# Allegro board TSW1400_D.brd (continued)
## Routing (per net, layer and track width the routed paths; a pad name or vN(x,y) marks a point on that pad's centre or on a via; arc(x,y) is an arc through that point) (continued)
N35303144: length 74.2
  TOP w0.254: U5.V11 v2(106.95,83.2) ; U5.AH18 v2(96.95,75.2) ; U5.U24 v2(108.95,69.2) ; U5.G18 v2(118.95,75.2)
  BOTTOM w0.254: 99.44,66.67 99.47,66.7 101.17,66.7 101.45,66.98 101.45,67.46 101.68,67.69 102.21,67.69 102.44,67.92 102.44,68.43 102.69,68.68 108.43,68.68 108.95,69.2 v2(108.95,69.2) 109.47,69.72 115.44,69.72 115.98,70.26 115.98,72.21 116.46,72.69 118.21,72.69 118.47,72.95 118.47,74.78 118.89,75.2 v2(118.95,75.2) ; 99.44,66.67 99.44,71.5 98.25,72.69 96.7,72.69 96.44,72.95 96.44,74.69 v2(96.95,75.2) 96.95,75.23 97.54,75.82 101.6,75.82 102.23,76.45 107.44,76.45 107.87,76.89 107.87,82.28 v2(106.95,83.2) ; 99.44,66.67 99.44,58.8 99.16,58.52
  BOTTOM w0.508: 99.16,58.52 96.77,56.13 C333.1 C330.1 FB4.2
N35337600: length 123.9
  TOP w0.254: U5.AC5 v2(101.95,89.2) ; U5.U5 v2(108.95,89.2) ; U5.AC30 v2(101.95,63.2) ; U5.U30 v2(108.95,63.2)
  L3-SIG1 w0.254: v2(108.95,89.2) 108.43,88.68 108.43,84.84 108.03,84.43 108.03,68.48 107.26,67.72 99.64,67.72 99.44,67.51 99.44,63.98 99.75,63.68 101.47,63.68 v2(101.95,63.2) 102.41,62.74 108.46,62.74 108.92,63.2 v2(108.95,63.2)
  L4-SIG2 w0.254: v2(108.95,89.2) 108.46,89.69 102.44,89.69 v2(101.95,89.2)
  L10-SIG4 w0.102: 101.94,89.2 v2(101.95,89.2) 101.95,90.1 101.94,90.11
  L10-SIG4 w0.254: 100.46,94.36 100.46,90.98 100.76,90.68 101.37,90.68 101.47,90.58 ; 99.52,94.36 99.44,94.28 99.44,91.01 100.74,89.71 101.14,89.71 101.66,89.2 101.94,89.2 101.94,90.11 101.47,90.58 ; 101.47,94.11 101.47,90.58
  L10-SIG4 w0.508: v1(56.39,112.01) 63.25,112.01 70.87,104.39 86.74,104.39 96.77,94.36 101.35,94.36 101.47,94.23 101.47,94.11
  vias: v1(54.1,112.01) v1(54.48,112.52) v1(54.48,111.51) v1(54.86,112.01) v1(55.24,112.52) v1(55.24,111.51) v1(55.63,112.01) v1(56.01,112.52) v1(56.01,111.51)
N38382982: length 1.7
  TOP w0.508: U2.4 196.02,139.51 C10.1
N38636606: length 1.8
  TOP w0.305: U8.1 2.55,73.16 2.13,72.75 R23.2
N38684744: length 1.9
  TOP w0.305: U8.13 4.36,76.03 3.53,76.86 C51.1
N38692023: length 8.7
  TOP w0.762: L6.1 3.95,79.62 5.11,78.46 C51.2
N38717147: length 5.5
  TOP w0.305: R29.2 6.99,77.47 5.86,76.34 U8.10
  TOP w0.508: R29.2 7.26,77.85 R30.1 R117.1
N38758692: length 2.6
  TOP w0.305: C58.1 6.73,76.33 6.36,75.95 U8.9
N38759863: length 6.3
  TOP w0.305: U8.8 7.48,74.66
  TOP w0.381: 7.48,74.66 8.13,75.31
  TOP w0.508: C57.1 11.53,75.31 8.13,75.31
  TOP w0.762: R27.1 11.58,75.31 C57.1
N38796735: length 5.6
  TOP w0.305: U8.7 7.74,73.16 v1(7.88,73.03)
  TOP w0.762: R24.1 10.82,72.26 v1(10.79,72.24) R28.1
  L3-SIG1 w0.762: v1(10.79,72.24) 9.68,72.24 8.89,73.03 v1(7.88,73.03)
N39329231: length 2.6
  TOP w0.762: TP15.1 R20.1
N39352684: length 3.1
  TOP w0.381: R21.1 27.05,116.81 R19.1 27.17,115.22 U7.16
N39357177: length 1.7
  TOP w0.381: C49.2 29.69,117.93 U7.15
N39394853: length 4.3
  TOP w0.381: U7.11 32.29,117.8 R22.2
  TOP w0.508: R22.2 32.59,117.83 32.92,118.16 32.92,118.26 33.91,119.25 R122.1
N39486748: length 2.3
  TOP w0.381: U9.3 31.64,125.49 31.11,124.97 C60.2
N39488974: length 3.9
  TOP w0.381: U9.2 31.75,126.14 31.4,126.49 R25.2
  TOP w0.508: R26.1 31.27,127.97
  TOP w0.762: 31.27,127.97 R25.2
N39500307: length 2.8
  TOP w0.381: C61.2 31.11,123.44 31.88,124.21 31.88,124.46 32.26,124.84 U9.4
N39520363: length 14
  TOP w0.432: U9.11 39.35,124.84 40.01,124.19 U9.10
  TOP w0.762: 40.01,124.19 40.14,124.05 C59.1 41.55,124.05 43.43,125.93 43.43,130.79 42.02,132.21 L7.1
N39536131: length 2
  TOP w0.381: U9.12 40.63,125.49 C59.2
N39697235: length 7.4
  TOP w0.762: C86.2 5.11,58.27 L10.1
N39697237: length 5.5
  TOP w0.305: U13.10 5.86,50.05 6.99,51.18 R43.2
  TOP w0.508: R123.1 R44.1 7.26,51.56 R43.2
N39697261: length 5.8
  TOP w0.305: v1(7.88,46.74) 7.74,46.87 U13.7
  TOP w0.762: R42.1 v1(10.95,45.95) 11.63,45.95 R40.1
  L3-SIG1 w0.762: v1(7.88,46.74) 9.02,46.74 9.8,45.95 v1(10.95,45.95)
N39697276: length 2.6
  TOP w0.305: C91.1 6.73,50.04 6.36,49.67 U13.9
N39697334: length 6.5
  TOP w0.305: U13.8 7.48,48.38
  TOP w0.381: 7.48,48.38 8.13,49.02
  TOP w0.508: 8.13,49.02 11.53,49.02 C90.1
  TOP w0.762: C90.1 13.23,49.02 R41.1
N39697425: length 1.9
  TOP w0.305: C86.1 3.53,50.57 4.36,49.74 U13.13
N39697499: length 1.8
  TOP w0.305: R39.2 2.13,46.46 2.55,46.87 U13.1
N39748772: length 14
  TOP w0.432: U15.11 57.9,124.84 58.55,124.19 U15.10
  TOP w0.762: L11.1 60.56,132.21 61.98,130.79 61.98,125.93 60.1,124.05 C97.1 58.68,124.05 58.55,124.19
N39748780: length 4.1
  TOP w0.381: R47.2 49.94,126.49 50.29,126.14 U15.2
  TOP w0.508: R48.1 49.81,127.97
  TOP w0.762: 49.81,127.97 R47.2
N39748835: length 2
  TOP w0.381: C97.2 59.17,125.49 U15.12
N39748872: length 2.3
  TOP w0.381: U15.3 50.18,125.49 49.66,124.97 C98.2
N39748888: length 2.8
  TOP w0.381: U15.4 50.8,124.84 50.42,124.46 50.42,124.21 49.66,123.44 C99.2
N40105653: length 5.6
  TOP w0.305: U10.7 7.74,111.01 v1(7.88,110.87)
  TOP w0.762: R35.1 v1(10.79,110.08) 11.51,110.08 R32.1
  L3-SIG1 w0.762: v1(7.88,110.87) 8.89,110.87 9.68,110.08 v1(10.79,110.08)
N40105663: length 8.7
  TOP w0.762: L8.1 3.95,117.59 5.11,116.43 C64.2
N40105684: length 5.5
  TOP w0.305: R33.2 6.99,115.32 5.86,114.19 U10.10
  TOP w0.508: R33.2 7.26,115.7 R36.1 R119.1
N40105708: length 2.6
  TOP w0.305: U10.9 6.36,113.8 6.73,114.17 C70.1
N40105747: length 6.3
  TOP w0.305: U10.8 7.48,112.51
  TOP w0.381: 7.48,112.51 8.13,113.16
  TOP w0.508: 8.13,113.16 11.53,113.16 C69.1
  TOP w0.762: C69.1 11.58,113.16 R34.1
N40105844: length 1.9
  TOP w0.305: U10.13 4.36,113.88 3.53,114.71 C64.1
N40105894: length 1.8
  TOP w0.305: R31.2 2.13,110.59 2.55,111.01 U10.1
N40477874: length 2.3
  TOP w0.381: U12.3 68.72,125.49 68.2,124.97 C83.2
N40477880: length 14
  TOP w0.432: U12.10 77.09,124.19 76.44,124.84 U12.11
  TOP w0.762: L9.1 79.1,132.21 80.52,130.79 80.52,125.93 78.64,124.05 C82.1 77.23,124.05 77.09,124.19
N40477882: length 3.9
  TOP w0.381: R37.2 68.48,126.49 68.83,126.14 U12.2
  TOP w0.508: R38.1 68.35,127.97
  TOP w0.762: 68.35,127.97 R37.2
N40477947: length 2
  TOP w0.381: C82.2 77.71,125.49 U12.12
N40477997: length 2.8
  TOP w0.381: C84.2 68.2,123.44 68.96,124.21 68.96,124.46 69.34,124.84 U12.4
N40549332: length 10.3
  TOP w0.178: v1(33.91,89.15) 34.04,89.02 U11.7 ; v1(34.29,84.05) 34.29,84.2 34.44,84.05 R120.2 R118.1 ; U11.9 34.04,88.02 v1(33.91,87.88)
  L3-SIG1 w0.178: v1(33.91,89.15) v1(33.91,87.88) 33.91,87.5 34.29,87.12 v1(34.29,84.05)
N40558976: length 1.5
  TOP w0.762: C74.1 14.66,113.18 R34.2
N41623470: length 17
  TOP w0.381: U16.2 92.96,136.9
  TOP w0.508: 92.96,136.9 92.96,135.76 91.44,134.24 87.22,134.24 ; 87.22,134.24 87.22,136.04 86.51,136.75 SJP1.1 ; 87.22,134.24 86.21,133.22 85.72,133.22 JP3.2
N41648199: length 29.3
  TOP w0.381: U17.2 185.04,87.38 184.94,87.27
  TOP w0.508: 176.59,87.19 177.67,88.27 178.18,88.77 178.18,93.22 179.71,94.74 SJP2.1 ; 176.59,87.19 177.93,85.85 183.51,85.85 184.94,87.27 ; 176.59,87.19 JP4.2
N44148054: length 1.8
  TOP w0.178: U5.B3 v2(123.95,91.2)
  BOTTOM w0.178: R90.2 124.7,91.95 v2(123.95,91.2)
N44148055: length 1.6
  TOP w0.178: U5.A3 v2(124.95,91.2)
  BOTTOM w0.178: R89.2 124.96,91.19 v2(124.95,91.2)
N44200403: length 46.6
  TOP w0.178: U5.T2 v2(109.95,92.2) ; U5.P1 v2(111.95,93.2) ; U5.AH1 v2(96.95,93.2) ; U5.F1 v2(119.95,93.2) ; U5.V2 v2(106.95,92.2) ; U5.P2 v2(111.95,92.2) ; U5.Y1 v2(104.95,93.2) ; U5.H2 v2(117.95,92.2) ; U5.V1 v2(106.95,93.2) ; U5.Y2 v2(104.95,92.2) ; U5.T1 v2(109.95,93.2) ; U5.H1 v2(117.95,93.2) ; U5.F2 v2(119.95,92.2) ; U5.AF1 v2(98.95,93.2) ; U5.AF2 v2(98.95,92.2) ; U5.AH2 v2(96.95,92.2)
  BOTTOM w0.178: v2(106.95,92.2) 106.93,92.2 106.43,91.69 105.46,91.69 v2(104.95,92.2) ; v2(106.95,92.2) 107.46,91.69 109.35,91.69 109.85,92.2 v2(109.95,92.2) ; v2(106.95,92.2) v2(106.95,93.2) ; v2(117.95,92.2) 118.46,91.69 119.38,91.69 119.89,92.2 v2(119.95,92.2) v2(119.95,93.2) ; v2(117.95,92.2) v2(117.95,93.2) ; v2(117.95,92.2) 117.85,92.2 117.35,91.69 112.46,91.69 v2(111.95,92.2) ; v2(104.95,92.2) v2(104.95,93.2) ; v2(104.95,92.2) 104.9,92.2 103.4,90.7 100.45,90.7 v2(98.95,92.2) ; v2(111.95,92.2) v2(111.95,93.2) ; v2(111.95,92.2) 111.88,92.2 111.38,91.69 110.46,91.69 v2(109.95,92.2) ; v2(109.95,92.2) v2(109.95,93.2) ; R91.1 96.9,93.25 v2(96.95,93.2) v2(96.95,92.2) 97.46,91.69 98.42,91.69 98.93,92.2 v2(98.95,92.2) ; v2(98.95,92.2) v2(98.95,93.2)
N44225882: length 26.5
  TOP w0.178: U5.M1 v2(113.95,93.2) ; U5.M2 v2(113.95,92.2) ; U5.AB2 v2(102.95,92.2) ; U5.AB1 v2(102.95,93.2) ; U5.K1 v2(115.95,93.2) ; U5.K2 v2(115.95,92.2) ; U5.AD2 v2(100.95,92.2) ; U5.AD1 v2(100.95,93.2)
  BOTTOM w0.178: v2(113.95,92.2) v2(113.95,93.2) ; v2(113.95,93.2) 113.94,93.2 113.41,93.73 103.48,93.73 v2(102.95,93.2) v2(102.95,92.2) 102.95,92.16 102.49,91.69 101.46,91.69 v2(100.95,92.2) v2(100.95,93.2) 100.97,93.22 R92.1 ; v2(113.95,93.2) 114.48,93.73 115.44,93.73 115.95,93.22 v2(115.95,93.2) v2(115.95,92.2)
N44253255: length 1.2
  TOP w0.178: U5.D34 v2(121.95,59.2)
  BOTTOM w0.178: R93.1 121.92,59.17 v2(121.95,59.2)
N44254573: length 1.3
  TOP w0.178: U5.AK34 v2(94.95,59.2)
  BOTTOM w0.178: v2(94.95,59.2) 94.95,58.72 R94.1
N44426490: length 4.7
  TOP w0.178: U18.5 59.13,119.1 R125.2 R124.1
N44456154: length 4.9
  TOP w0.254: U18.3 59.79,117.12 59.94,116.97 59.94,114.68 59.31,114.05 R96.2
N44466162: length 3.2
  TOP w0.254: 54.51,117.12 R97.1 ; 54.51,117.12 R98.2 ; 54.51,117.12 54.51,117.12 U18.8
N44506277: length 2.9
  TOP w0.254: C337.1 55.24,118.64 55.24,117.86 55.48,117.62 U18.7
N44658612: length 1.3
  TOP w0.178: U5.E9 v2(120.95,85.2)
  BOTTOM w0.178: R95.1 120.97,85.22 v2(120.95,85.2)
N45362819: length 24.8
  TOP w0.457: U15.7 50.53,122.89 R114.1 ; U12.7 69.07,122.89 R115.1
  TOP w0.508: v1(68.07,121.28) 68.07,121.89 R115.1 ; R114.1 v1(49.56,121.28)
  BOTTOM w0.508: v1(68.07,121.28) v1(49.56,121.28)
N45364246: length 4.9
  TOP w0.457: U9.7 31.98,122.89 R113.1
  TOP w0.508: R113.1 31.78,121.16 R121.1
N45543111: length 1.9
  BOTTOM w0.178: J13.9 R129.2
N45543118: length 1.9
  BOTTOM w0.178: 141.6,38.1 R130.2
N45543130: length 1.8
  BOTTOM w0.178: 141.6,40.64 R131.2
N45543159: length 1.8
  BOTTOM w0.178: 139.06,40.64 R132.2
N45543649: length 1.4
  TOP w0.178: DN2.2 97.98,106.87 C352.1
N45582695: length 6.5
  TOP w0.178: SJP1.2 85.09,140.46 85.47,140.84 87.25,140.84 87.76,140.33 U16.10
N45584475: length 2.2
  TOP w0.178: U17.10 SJP2.2
N45611700: length 2.3
  TOP w0.178: R72.2 D7.1
N45611745: length 10.8
  TOP w0.178: SW3.3 SW3.4 153.96,101 R85.2 153.92,99.59 C339.1 153.9,98.2 153.92,98.17
N45611776: length 10.8
  TOP w0.178: SW5.3 SW5.4 172.89,101.13 172.85,100.97 172.85,99.59 C341.1 172.82,98.2 172.85,98.17
N45611858: length 10.8
  TOP w0.178: 135.13,98.17 135.1,98.2 C342.1 135.13,99.59 R88.2 135.17,101.13 SW6.4 SW6.3
N45611860: length 2.3
  TOP w0.178: R69.2 D3.1
N45611894: length 10.8
  TOP w0.178: SW4.3 SW4.4 163.23,101 R86.2 163.19,99.59 C340.1 163.17,98.2 163.19,98.17
N45612012: length 20.1
  TOP w0.178: R79.2 28.7,18.41 29.21,17.91 U1.3 U1.6 ; R79.2 28.71,18.91 U1.1 ; R79.2 28.07,18.92 25.78,16.64 25.78,12.83 27.43,11.18 29.65,11.18 SW7.2
N45612026: length 33.5
  L4-SIG2 w0.508: SW7.8 30.91,12.49 32.51,14.1 35.31,14.1 36.91,12.49 SW7.11 42.42,17.92 42.42,28.96 J18.1
N45612034: length 17.8
  TOP w0.178: U14.1 35.57,18.91 R77.2 35.69,18.41 36.19,17.91 U14.3 U14.6 39.91,17.91 40.39,17.91 41.02,17.27 41.02,12.45 39.75,11.18 37.85,11.18 36.91,10.24 SW7.5
N45612058: length 10.8
  TOP w0.178: SW2.3 SW2.4 144.56,101.13 R84.2 144.53,99.59 C338.1 144.5,98.2 144.53,98.17
N45612265: length 2.3
  TOP w0.178: R70.2 D4.1
N45612267: length 2.3
  TOP w0.178: R71.2 D5.1
N45612353: length 2.3
  TOP w0.178: R74.2 D8.1
N45612355: length 2.3
  TOP w0.178: R75.2 D9.1
N45612432: length 2.3
  TOP w0.178: R68.2 D2.1
N45612555: length 2.3
  TOP w0.178: R73.2 D6.1
N45612557: length 2.6
  TOP w0.178: D1.1 R67.1
N45629411: length 4.8
  TOP w0.178: U5.B2 v2(123.95,92.2)
  BOTTOM w0.178: R138.1 R137.2 122.43,92.96 122.68,92.71 123.44,92.71 v2(123.95,92.2)
N45629497: length 5.9
  TOP w0.178: U5.C3 v2(122.95,91.2)
  BOTTOM w0.178: v2(122.95,91.2) 122.94,91.19 122.94,90.42 123.7,89.66 R139.1 R140.2
N45629519: length 3.8
  TOP w0.178: U5.B1 v2(123.95,93.2)
  BOTTOM w0.178: v2(123.95,93.2) 124.32,93.57 124.94,93.57 R141.2 R142.1
N45638501: length 1.9
  TOP w0.178: U19.8 R134.2
N45639686: length 26.1
  TOP w0.406: 195.66,103.68 196.22,103.12 197.99,103.12 198.54,103.68 ; 195.66,103.68 195.16,104.18 J4.1 ; 195.66,103.68 J4.3 ; 198.54,103.68 199.04,104.18 J4.2 ; 198.54,103.68 J4.4
  TOP w0.508: F2.2 R65.2 ; J4.1 194.08,104.01
  TOP w1.016: 194.08,104.01 192.28,104.01
  TOP w1.524: 192.28,104.01 186.81,109.48 F2.2
N45639690: length 2.1
  TOP w0.508: D10.1 182.37,114.87 R65.1
N45747552: length 4
  TOP w0.178: U20.10 25,140.32 25.4,140.72 25.4,141.99 26.14,142.72 R148.1
N45747567: length 1.9
  TOP w0.178: U20.5 16.85,140.32 C295.1
N45747801: length 4.5
  TOP w0.178: U20.4 R158.1 15.01,140.97 R157.2
N45748253: length 3.8
  TOP w0.508: R146.1 26.11,139.67 U20.9
  TOP w0.762: R146.1 R145.2
N45782435: length 1.3
  TOP w0.178: U5.AN2 v2(91.95,92.2)
  BOTTOM w0.178: v2(91.95,92.2) 91.95,92.2 R143.2
N45835930: length 2.7
  TOP w0.762: U6.5 77.41,109.5 77.05,109.86 Y2.3
N45836337: length 51
  TOP w0.178: JP8.2 131.83,116.71 131.83,97.66 132.21,97.28 132.21,85.46 v2(124.95,78.2) U5.A16 ; U5.F17 v2(119.95,77.2)
  BOTTOM w0.178: v2(119.95,77.2) 120,77.2 120.52,77.72 120.52,78.49 120.78,78.74 124.41,78.74 v2(124.95,78.2)
N45837320: length 4.1
  TOP w0.508: R155.1 47.5,26.29 ; 47.5,26.29 R116.2 ; 47.5,26.29 J18.3
N45842022: length 10.1
  TOP w0.178: R154.1 34.91,15.33 SW7.10
  L9-SIG3 w0.178: SW7.10 33.48,13.84 30.35,13.84 28.92,12.41 SW7.7
N45842530: length 11.6
  TOP w0.508: v1(90.55,52.2) v1(90.93,51.82) SJP3.2
  BOTTOM w0.508: v1(90.93,51.82) v1(90.55,52.2) 89.92,52.83 89.92,56.64 90.42,57.15 R144.2
N45845005: length 1.2
  TOP w0.254: U5.AN33 92.45,60.71 91.96,61.2 v2(91.95,61.2)
  BOTTOM w0.508: v2(91.95,61.2) 91.94,61.21 R144.1
N45846780: length 2.6
  TOP w0.178: R147.1 25.29,139.02 U20.8
N387611130: length 1.5
  TOP w0.762: C63.1 14.66,75.34 R27.2
N396973600: length 1.6
  TOP w0.762: C93.1 16.31,49.05 R41.2

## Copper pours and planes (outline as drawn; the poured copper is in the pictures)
0.9V on TOP (solid shape): 24.64,71.63 12.7,71.63 12.7,72.77 19.56,72.77 19.56,78.36 17.65,80.26 15.49,80.26 11.94,83.82 11.94,87.38 24.64,87.38
0.9V on L7-PWR2: 103.5,73.66 96.39,73.66 96.39,78.49 96.65,78.74 97.41,78.74 97.41,79.76 97.16,80.01 97.16,82.55 99.06,82.55 99.06,93.34 89.03,93.34 89.03,90.81 89.53,90.81 89.53,89.53 83.19,89.53 83.19,103.5 91.44,103.5 91.44,99.69 107.31,99.69 107.31,91.44 104.65,91.44 104.65,87 112.39,87 112.39,95.12 110.87,95.12 110.87,100.33 140.97,100.33 140.97,79.38 129.54,79.38 129.54,90.68 126.36,90.68 126.36,95.25 117.09,95.25 117.09,79.38 111.76,79.38 111.76,59.69 121.92,59.69 121.92,48.9 20.95,48.9 20.95,87.63 26.67,87.63 26.67,58.42 82.93,58.42 85.6,61.09 87.25,61.09 88.01,61.85 89.66,61.85 89.66,53.09 100.33,53.09 100.33,66.67 100.46,66.8 100.46,67.44 100.33,67.56 100.33,69.22 103.5,69.22
0.9V_DDR on TOP: 48.77,65.91 48.77,87.5 43.05,87.5 42.16,88.39 42.16,88.65 43.05,89.53 51.31,89.53 51.31,65.91
0.9V_DDR on BOTTOM: 51.31,65.91 48.77,65.91 48.77,86.74 43.18,86.74 43.18,89.66 39.12,89.66 39.12,90.42 51.31,90.42
1.1V on TOP (solid shape): 28.83,111.76 29.84,111.76 29.84,110.74 22.35,110.74 22.35,114.05 28.83,114.05
1.1V on L6-PWR1: 102.23,64.39 106.68,68.83 109.86,68.83 110.36,69.34 110.36,72.01 110.24,72.14 110.24,81.03 110.36,81.15 110.36,83.19 109.98,83.57 107.19,83.57 106.3,84.45 103.12,84.45 103.12,90.04 113.67,90.04 113.67,86.61 111.76,86.61 111.76,64.77 113.67,64.77 113.67,59.69 107.95,59.69 107.95,42.55 31.75,42.55 31.75,48.9 10.79,48.9 10.79,67.94 35.56,67.94 35.56,92.08 26.04,92.08 26.04,109.98 20.32,109.98 20.32,115.95 30.48,115.95 30.48,112.39 31.11,112.39 31.11,97.79 43.18,97.79 43.18,60.33 16.51,60.33 16.51,53.98 59.69,53.98 59.69,50.8 90.81,50.8 90.81,47.62 102.23,47.62
1.5V on TOP (solid shape): 36.83,128.02 33.53,128.02 33.53,126.62 32.51,126.62 32.51,129.41 27.43,129.41 27.43,133.1 36.83,133.1
1.5V on L7-PWR2: 105.28,87.63 105.28,90.81 107.95,90.81 107.95,100.33 92.08,100.33 92.08,104.14 82.55,104.14 82.55,88.9 83.19,88.9 83.19,75.56 77.47,75.56 77.47,106.05 93.98,106.05 93.98,102.62 103.5,102.62 103.5,117.6 92.71,117.6 92.71,114.3 35.18,114.3 31.11,118.36 31.11,124.21 24.51,130.81 24.51,132.72 25.15,133.35 40.01,133.35 40.01,123.83 44.45,119.38 110.24,119.38 110.24,94.49 111.76,94.49 111.76,87.63
1.8V on TOP (solid shape): 42.04,87.25 42.29,86.74 42.29,86.23 41.91,85.72 40.89,85.72 40.51,86.23 40.51,86.74 40.77,87.25 40.77,88.11 42.04,88.11
1.8V on TOP (solid shape): 25.53,120.14 21.21,116.46 21.21,109.47 12.7,109.47 12.7,110.62 19.56,110.62 19.56,116.33 14.99,121.16 12.06,121.16 12.06,125.09 25.53,125.09
1.8V on L7-PWR2: 38.1,92.71 38.1,65.28 87.12,65.28 88.01,64.39 89.03,64.39 90.3,65.66 93.6,65.66 93.6,68.33 96.39,68.33 96.39,65.41 99.69,65.41 99.69,67.82 99.57,67.94 99.57,68.58 99.69,68.71 99.69,69.85 102.87,69.85 102.87,73.03 95.76,73.03 95.76,77.47 95.5,77.72 95.5,78.61 96.01,79.12 96.52,79.12 96.52,83.82 93.73,83.82 93.73,85.72 87.63,85.72 87.63,69.85 71.12,69.85 71.12,106.68 25.4,106.68 25.4,118.87 26.67,118.87 26.67,120.65 25.4,120.65 20.07,125.98 20.07,134.11 22.48,136.53 78.11,136.53 81.92,132.72 129.16,132.72 129.16,117.98 160.02,117.98 160.02,88.27 174.62,88.27 174.62,147.96 86.36,147.96 82.55,151.76 0.64,151.76 0.64,89.53 12.7,89.53 15.88,92.71 ; 3 cut-outs
2.5V on TOP (solid shape): 35.31,112.65 36.2,112.01 36.2,111.12 35.43,110.74 34.54,110.74 33.78,111.12 33.78,112.01 34.54,112.65 34.54,113.41 35.31,113.41
2.5V on TOP (solid shape): 23.88,45.21 12.83,45.21 12.83,46.35 19.68,46.35 19.68,52.45 18.16,53.98 14.29,53.98 11.81,56.52 9.65,56.52 9.65,59.18 23.88,59.18
2.5V on L6-PWR1: 43.81,59.69 43.81,98.42 31.75,98.42 31.75,113.03 31.11,113.03 31.11,120.55 33.15,120.55 33.15,115.57 54.61,115.57 54.61,102.87 133.99,102.87 133.99,53.98 108.58,53.98 108.58,59.05 114.3,59.05 114.3,65.41 112.39,65.41 112.39,85.98 114.3,85.98 114.3,90.68 102.49,90.68 102.49,83.82 106.17,83.82 106.93,83.06 109.73,83.06 110.11,82.68 110.11,81.66 109.6,81.15 109.6,72.14 110.11,71.63 110.11,69.85 109.73,69.47 106.43,69.47 101.6,64.64 101.6,48.26 91.44,48.26 91.44,51.44 60.33,51.44 60.33,54.61 17.14,54.61 17.14,59.69
3.0V on TOP (solid shape): 55.37,128.02 52.07,128.02 52.07,126.62 51.05,126.62 51.05,129.41 45.97,129.41 45.97,133.1 55.37,133.1
3.0V on L7-PWR2: outline of 91 points within 13.34,34.29 186.06,135.89
3.3V on TOP (solid shape): 73.91,128.02 70.61,128.02 70.61,126.62 69.6,126.62 69.6,129.41 64.52,129.41 64.52,133.1 73.91,133.1
3.3V on L6-PWR1: 154.94,93.98 134.62,93.98 134.62,103.5 55.24,103.5 55.24,121.28 63.37,121.28 63.37,118.11 59.69,118.11 59.69,113.67 66.67,113.67 66.67,118.75 80.64,118.75 80.64,130.81 73.41,130.81 73.41,129.29 63.63,129.29 63.63,130.81 29.34,130.81 29.34,151.76 90.17,151.76 90.17,128.91 97.16,128.91 97.16,140.34 167,140.34 167,114.3 175.9,114.3 175.9,59.82 187.83,59.82 187.83,33.15 198.25,33.15 198.25,20.19 187.83,20.19 187.83,10.92 154.94,10.92 ; 1 cut-out
3.3V_USB on L6-PWR1: 167.64,140.97 96.52,140.97 96.52,129.54 90.81,129.54 90.81,149.86 193.68,149.86 193.68,143.51 201.29,143.51 201.29,86.36 176.53,86.36 176.53,114.94 167.64,114.94
5V_IN on TOP (solid shape): 13.84,141.73 10.92,141.73 10.92,142.75 13.84,142.75
5V_IN on TOP (solid shape): 8.89,109.6 6.35,109.6 6.22,109.73 6.22,110.36 8.89,110.36
5V_IN on TOP (solid shape): 8.89,71.75 6.35,71.75 6.22,71.88 6.22,72.52 8.89,72.52
5V_IN on TOP (solid shape): 8.89,45.47 6.35,45.47 6.22,45.59 6.22,46.23 8.89,46.23
5V_IN on TOP (solid shape): 8.89,129.41 5.33,129.41 5.33,133.35 8.89,133.35
5V_IN on TOP (solid shape): 41.4,129.41 41.4,127.64 41.02,127.25 41.02,126.75 40.13,126.75 40.13,129.41 40.26,129.54 41.27,129.54
5V_IN on TOP (solid shape): 59.94,129.41 59.94,127.64 59.56,127.25 59.56,126.75 58.67,126.75 58.67,129.41 58.8,129.54 59.82,129.54
5V_IN on TOP (solid shape): 78.49,129.41 78.49,127.64 78.11,127.25 78.11,126.75 77.22,126.75 77.22,129.41 77.34,129.54 78.36,129.54
5V_IN on TOP (solid shape): 36.07,117.98 36.07,117.09 35.26,116.46 35.26,115.7 34.54,115.7 34.54,116.46 33.66,117.09 33.66,117.98 34.42,118.36 35.31,118.36
5V_IN on TOP (solid shape): 5.97,108.2 6.22,108.2 6.86,107.7 6.86,106.81 6.48,106.43 4.83,106.43 4.45,106.81 4.45,107.7 5.08,108.2 5.31,108.2 5.31,110.24 5.97,110.24
5V_IN on TOP (solid shape): 5.97,70.36 6.22,70.36 6.86,69.85 6.86,68.96 6.48,68.58 4.83,68.58 4.45,68.96 4.45,69.85 5.08,70.36 5.3,70.36 5.3,72.39 5.97,72.39
5V_IN on TOP (solid shape): 5.97,44.07 6.22,44.07 6.86,43.56 6.86,42.67 6.48,42.29 4.83,42.29 4.45,42.67 4.45,43.56 5.08,44.07 5.32,44.07 5.32,46.1 5.97,46.1
5V_IN on TOP (solid shape): 25.4,33.02 18.03,33.02 17.65,32.64 17.65,26.92 17.02,26.29 17.02,19.94 12.7,19.94 12.7,40.01 25.4,40.01
5V_IN on TOP (solid shape): 35.69,87.12 35.31,86.74 34.8,86.74 33.91,85.85 33.91,85.6 33.53,85.09 32.51,85.09 32.13,85.6 32.13,86.11 32.38,86.49 32.38,87.38 33.53,87.38 33.66,87.25 34.04,87.25 34.42,87.63 35.69,87.63
5V_IN on L6-PWR1: 33.66,121.16 30.48,121.16 30.48,116.59 19.68,116.59 19.68,109.35 25.4,109.35 25.4,91.44 34.92,91.44 34.92,68.58 10.16,68.58 10.16,48.26 31.11,48.26 31.11,41.91 52.07,41.91 52.07,15.88 0.64,15.88 0.64,151.76 28.7,151.76 28.7,130.18 63.12,130.18 63.12,128.78 73.91,128.78 73.91,130.18 80.01,130.18 80.01,119.38 66.04,119.38 66.04,114.3 60.33,114.3 60.33,117.47 64.01,117.47 64.01,121.92 54.61,121.92 54.61,116.2 33.66,116.2 ; 1 cut-out
6.0V_OUT on TOP (solid shape): 185.29,100.97 179.2,100.97 179.2,105.28 185.29,105.28
6.0V_OUT on TOP (solid shape): 32.13,146.81 32.13,142.37 33.15,141.35 33.15,138.68 30.35,138.68 30.35,140.46 29.97,140.84 29.21,140.84 29.21,145.16 19.81,145.16 19.81,149.99 28.57,149.99
6.0V_OUT on BOTTOM: 179.32,105.28 178.05,104.01 178.05,102.23 179.32,100.97 181.36,100.97 181.36,105.28
6.0V_OUT on BOTTOM: 30.35,141.48 30.35,138.68 30.86,138.18 32.64,138.18 33.15,138.68 33.15,141.48
GND on TOP (solid shape): 7.51,111.91 6.78,111.91 6.78,111.61 7.51,111.61 7.51,111.49 3.21,111.49 3.21,111.61 3.93,111.61 3.93,111.91 3.21,111.91 3.21,111.99 7.51,111.99
GND on TOP (solid shape): 7.51,74.06 6.78,74.06 6.78,73.76 7.51,73.76 7.51,73.65 3.21,73.65 3.21,73.76 3.93,73.76 3.93,74.06 3.21,74.06 3.21,74.15 7.51,74.15
GND on TOP (solid shape): 7.51,47.78 6.78,47.78 6.78,47.47 7.51,47.47 7.51,47.36 3.21,47.36 3.21,47.47 3.93,47.47 3.93,47.78 3.21,47.78 3.21,47.85 7.51,47.85
GND on TOP: 0.38,96.8 15.24,99.19 0.38,101.57 0.38,152.02 56.5,152.02 57.91,136.9 59.32,152.02 205.36,152.02 205.36,0.38 0.38,0.38 ; 65 cut-outs
GND on BOTTOM: 0.38,0.38 0.38,96.8 15.24,99.19 0.38,101.57 0.38,152.02 56.48,152.02 57.91,136.9 59.35,152.02 205.36,152.02 205.36,0.38 ; 55 cut-outs
GND on L2-GND1: 0.38,152.02 0.38,0.38 205.36,0.38 205.36,152.02 ; 2 cut-outs
GND on L5-GND2, L11-GND4: 0.38,152.02 0.38,0.38 205.36,0.38 205.36,152.02 ; 1 cut-out
GND on L6-PWR1: 90.42,152.02 90.42,150.11 193.93,150.11 193.93,143.76 201.55,143.76 201.55,86.11 176.28,86.11 176.28,60.2 188.21,60.2 188.21,33.53 198.5,33.53 198.5,19.81 188.21,19.81 188.21,10.54 154.69,10.54 154.69,93.73 134.24,93.73 134.24,53.72 108.2,53.72 108.2,42.29 52.32,42.29 52.32,15.62 0.38,15.62 0.38,0.38 205.36,0.38 205.36,152.02
GND on L7-PWR2: 82.8,152.02 82.8,151.89 86.49,148.21 174.88,148.21 174.88,96.14 186.31,96.14 186.31,34.04 13.08,34.04 13.08,89.28 0.38,89.28 0.38,0.38 205.36,0.38 205.36,152.02
GND on L8-GND3: 0.38,152.02 0.38,0.38 205.36,0.38 205.36,152.02 ; 1 cut-out
N35337600 on TOP: 57.28,114.43 56.39,115.32 56.39,116.71 55.75,116.71 55.24,116.2 55.24,115.32 53.85,115.32 53.85,111.76 54.36,111.25 56.13,111.25 57.28,112.39
N35337600 on L10-SIG4: 56.64,111.76 56.64,112.27 56.13,112.78 54.36,112.78 53.85,112.27 53.85,111.76 54.36,111.25 56.13,111.25
N38692023 on TOP (solid shape): 5.43,75.44 4.79,75.44 4.8,77.6 5.43,77.6
N39697235 on TOP (solid shape): 5.44,49.15 4.77,49.15 4.78,51.31 5.44,51.31
N40105663 on TOP (solid shape): 5.43,113.28 4.78,113.29 4.78,115.44 5.43,115.44
N40516729 on TOP (solid shape): 10.54,17.27 18.29,17.27 18.8,16.76 18.8,12.95 17.27,11.43 12.8,11.43 10.39,13.84 6.35,13.84 6.35,23.88 10.54,23.88
N45748163 on TOP (solid shape): 18.92,142.24 17.53,142.24 14.1,145.29 12.7,145.29 9.78,142.88 9.78,140.97 5.33,140.97 5.33,143.13 12.7,149.35 18.92,149.35

Small or netless copper shapes (teardrops, artwork), in the pictures only: 50 on TOP, 11 on BOTTOM, 9 on L3-SIG1

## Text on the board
BOTTOM: LAYER 12 (BOTTOM SIDE)
Package Geometry/Pastemask Bottom: PASTEMASK BOTTOM
Ref Des/Silkscreen Bottom: 79 | 69 | 59 | 49 | 39 | 29 | 19 | 9 | 1 | SILKSCREEN BOTTOM
User.Comments: TEXAS INSTRUMENTS | TSW1400 REV D | SOLDERMASK TOP | SOLDERMASK BOTTOM
TOP: LAYER 1  (TOP SIDE)
Ref Des/Assembly Top: 2 | 1 | 60 | 59
Package Geometry/Pastemask Top: PASTEMASK TOP
Ref Des/Silkscreen Top: DDR2-SODIMM | 3.0V | GND | 1.8V | "1" | "0" | USER DIP[0:3] | 79 | 69 | 59 | 49 | 39 | 29 | 19 | 9 | 1 | SILKSCREEN TOP | +5V_IN | ON | OFF | 5V | TSW1400 REV D | J3 | ADC_INTERFACE | CMOS_INTERFACE | J1
L2-GND1: LAYER 2  (GND1)
L3-SIG1: LAYER 3  (SIG1)
L4-SIG2: LAYER 4  (SIG2)
L5-GND2: LAYER 5  (GND2)
L6-PWR1: LAYER 6  (PWR1)
L7-PWR2: LAYER 7  (PWR2)
L8-GND3: LAYER 8  (GND3)
L9-SIG3: LAYER 9  (SIG3)
L10-SIG4: LAYER 10 (SIG4)
L11-GND4: LAYER 11 (GND4)
User.45: C18 | C14 | C16 | C17 | C172 | C174 | C163 | C134 | C117 | C166 | C150 | C167 | C168 | C149 | C173 | C178 | C37 | C36 | C7 | FB2 | FB1 | FB5 | C146 | R139 | R140 | R141 | 1 | 2 | R142 | R55 | C259 | C258 | R138 | R137 | R93 | C129 | C243 | C141 | C106 | C241 | C249 | C239 | C260 | C230 | C113 | C127 | C242 | C107 | C240 | C233 | 59 | 60 | C110 | C214 | C278 | C222 | C190 | C207 | C130 | J3 | C104 | C237 | C165 | C223 | C235 | C286 | 61 | 62 | C234 | C111 | C112 | C105 | C126 | C238 | C283 | C143 | R92 | C182 | C212 | C218 | C247 | R91 | C333 | C330 | R94 | C184 | R49 | C121 | R51 | C271 | C119 | R144 | C189 | R143 | R50 | 119 | 120 | C116 | C115 | R18 | R17 | C145 | C147 | C199 | C200 | C197 | C198 | FB6 | C23 | C24 | C25 | C26 | C27 | C22 | R10 | R9 | C39 | C38 | C30 | C31 | C32 | C33 | C28 | C29 | C186 | C251 | C138 | C252 | C125 | C157 | C136 | C280 | C289 | C281 | C279 | C135 | C232 | C267 | C274 | C268 | C265 | C120 | C269 | C3 | C5 | C6 | C19 | R4 | C1 | C13 | C2 | C15 | C155 | C176 | C154 | C169 | C153 | C156 | C171 | C177 | C109 | C124 | C170 | C102 | C139 | C152 | C175 | C151 | C4 | R129 | R131 | R130 | R132 | C329 | C332 | R89 | R90 | C162 | C204 | C255 | C257 | R95 | C148 | C203 | C248 | C202 | R105 | R104 | C254 | C128 | C250 | C253 | C103 | C195 | C221 | C185 | C206 | C187 | C159 | C183 | C284 | C192 | C263 | C208 | C205 | C196 | C262 | C231 | C181 | C261 | C236 | C108 | C160 | C188 | C209 | C226 | C225 | C217 | C213 | C210 | C215 | C161 | C194 | C216 | C164 | C193 | C228 | C220 | C211 | C179 | C158 | C180 | C201 | R54 | R56 | C101 | C246 | C244 | C133 | C288 | C219 | C245 | FB4 | C131 | C224 | C122 | C144 | C331 | C328 | C34 | C114 | C35 | C140 | C132 | C277 | C137 | C287 | R136 | C282 | C229 | C285 | C276 | C266 | C275 | C191 | C290 | C270 | C118 | C273 | C272 | C123 | R135 | J1 | MP2 | MP3 | SEE DETAIL A | X PL | INSTALL STANDOFFS (MP3) AND SCREWS (MP2) AS SHOWN. | PC BOARD TOP SIDE | P. LARSON | H. FRAZ | 01/05/2011 | TOP SIDE | Pb | DETAIL A (SIDE VIEW) - NO SCALE | BOTTOM SIDE | D | C | B | A | 8 | 7 | 6 | 5 | 4 | 3 | 1.  REFER TO ODB++ FILE FOR SPECIFIC COMPONENT LOCATION INFORMATION. | 2   FINISHED ASSEMBLY MUST BE RoHS COMPLIANT. LABEL OR MARK 'PB FREE' IN THIS AREA ON TOP SIDE. | THIS DRAWING IS INTENDED TO HELP IN THE ASSEMBLY OF THE DESIGN. | OUTER LAYERS USING A          mil TRACE WIDTH SHALL BE  50ohms SINGLE ENDED, +/- 10% TOLERANCE. | 6.5 | DO NOT SCALE DRAWING | UNLESS OTHERWISE SPECIFIED | DIMENSIONS ARE IN INCHES | TOLERANCES ARE: | FRACTIONS | MATERIAL | FINISH | +/- | SEE NOTES 7, 8, 9 | SEE NOTE 5 | .XXX +/-.005 | .XX +/-.01 | DECIMALS | ANGLES | APPROVALS | DRAWN | ENGR | CONTRACT NO. | ZONE | DATE | LTR | SIZE | SCALE | CODE IDENT NO. | NONE | TEXAS INSTRUMENTS INC. | DESCRIPTION | ASSEMBLY DRAWING | REVISIONS | TSW1400 | DRAWING NO. | SHEET 1 OF 1 | APPROVED | REV. | FIGURE | 8.0 | 10.0 | 32.0 | 35.0 | 38.0 | 40.0 | 50.0 | 62.0 | 67.0 | 120.0 | 140.0 | 250.0 | 18.0 | 44.0 | 47.0 | 63.0 | 110.0 | 125.0 | 156.0 | DRILL CHART: TOP to BOTTOM | ALL UNITS ARE IN MILS | TOLERANCE | +3.0/-8.0 | +3.0/-10.0 | +0.0/-0.0 | +3.0/-3.0 | PLATED | NON-PLATED | QTY | 1087 | 2102 | 12 | 10 | 118 | 14 | 24
